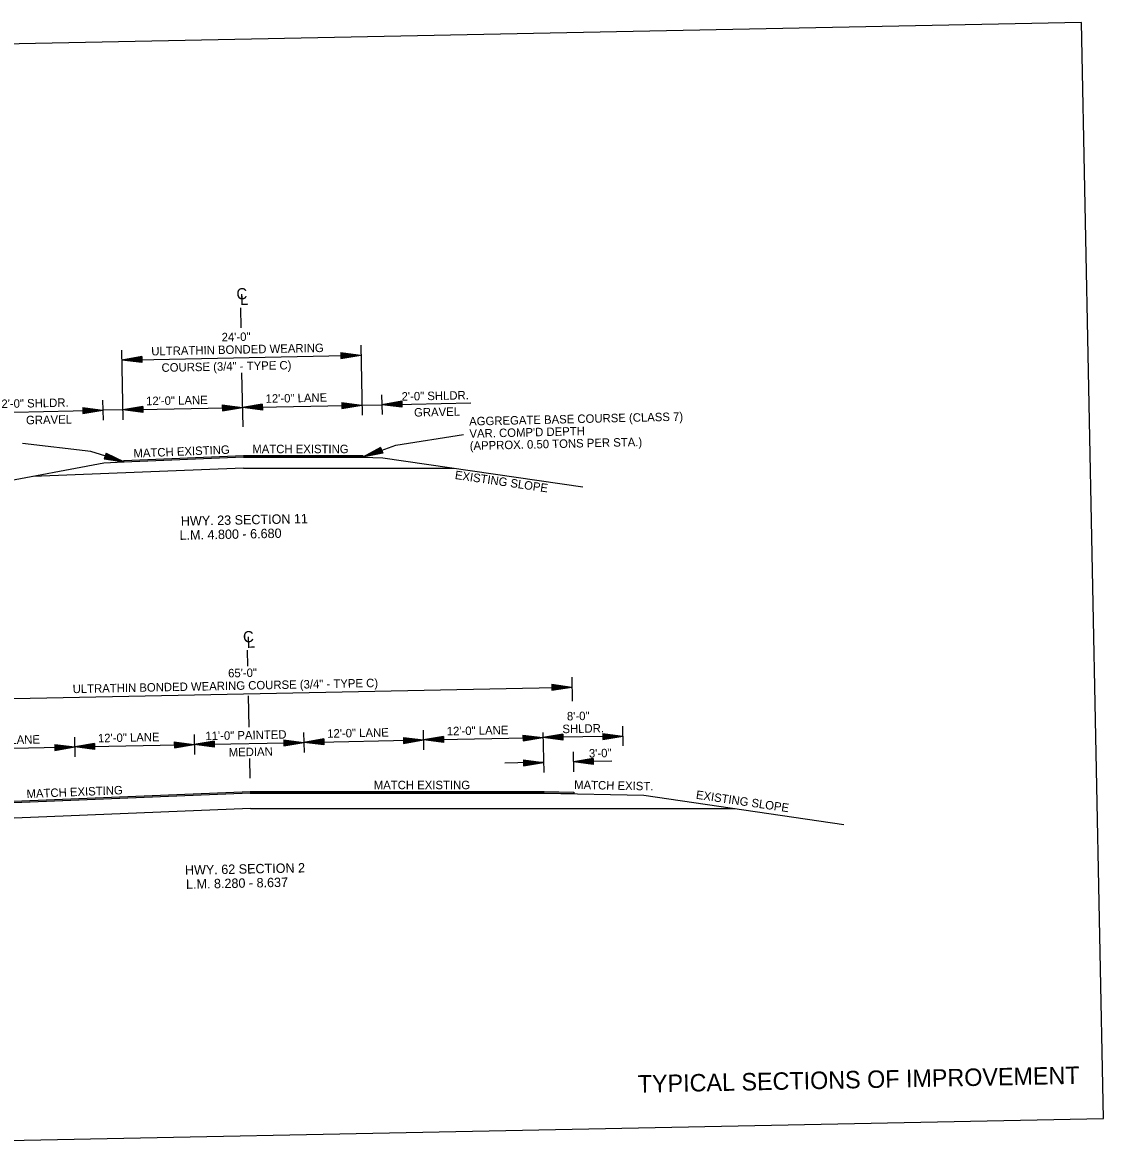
# Model space of a CAD drawing. Extents: x 174 to 869, y -36 to 177.
# Drawn here: x 760.3 to 868.8, y 64.1 to 177.4 of the extents above; entities that cross this region are included whole.
import ezdxf

# ---------------------------------------------------------------- set-up
doc = ezdxf.new("R2010")
doc.units = 0
for name, color, linetype in [('Default', 7, 'Continuous'), ('DSN_DRFT_Common-Annotations', 7, 'Continuous'), ('DSN_DRFT_Common-Line', 7, 'Continuous'), ('DSN_DRFT_Dimension', 7, 'Continuous'), ('SHET_Border-Text', 7, 'Continuous')]:
    doc.layers.add(name, color=color, linetype=linetype)

msp = doc.modelspace()

# ---------------------------------------------------------------- linework, layer by layer
at = {"layer": 'Default'}
for p, q in [((797.77, 135.02), (804.58, 136.09)), ((767.18, 134.4), (760.32, 135.21)), ((794.47, 133.82), (797.77, 135.02)), ((770.52, 133.35), (767.18, 134.4)), ((768.7, 134.24), (768.52, 133.66)), ((768.57, 133.81), (769.55, 133.65)), ((768.58, 133.86), (769.23, 133.75)), ((768.6, 133.9), (768.91, 133.85)), ((768.63, 133.99), (768.91, 133.85)), ((768.64, 134.04), (769.23, 133.75)), ((768.66, 134.09), (769.55, 133.65)), ((768.67, 134.14), (769.87, 133.55)), ((768.69, 134.19), (770.2, 133.45)), ((768.7, 134.24), (770.52, 133.35)), ((796.25, 134.79), (794.47, 133.82)), ((796.46, 134.22), (794.47, 133.82)), ((796.27, 134.74), (794.79, 133.94)), ((796.44, 134.27), (794.79, 133.94)), ((796.29, 134.69), (795.11, 134.05)), ((796.42, 134.32), (795.11, 134.05)), ((796.3, 134.64), (795.42, 134.17)), ((796.4, 134.36), (795.42, 134.17)), ((796.32, 134.6), (795.74, 134.28)), ((796.39, 134.41), (795.74, 134.28)), ((796.34, 134.55), (796.06, 134.4)), ((796.37, 134.46), (796.06, 134.4)), ((796.25, 134.79), (796.46, 134.22)), ((768.52, 133.66), (770.52, 133.35)), ((768.54, 133.71), (770.2, 133.45)), ((768.55, 133.76), (769.87, 133.55))]:
    msp.add_line(p, q, dxfattribs=at)
at = {"layer": 'DSN_DRFT_Common-Line'}
for p, q in [((782.17, 148.82), (782.21, 146.8)), ((770.25, 144.58), (770.39, 137.58)), ((794.25, 145.06), (794.39, 138.06)), ((782.3, 142.28), (782.41, 136.87)), ((768.35, 139.54), (768.39, 137.54)), ((796.35, 140.1), (796.39, 138.1)), ((782.47, 133.82), (770.48, 133.34)), ((782.47, 133.82), (794.47, 133.82)), ((794.47, 133.82), (796.47, 133.78)), ((768.48, 133.22), (748.55, 129.49)), ((782.49, 132.74), (761.39, 131.9)), ((770.48, 133.34), (768.48, 133.22)), ((782.49, 132.74), (803.61, 132.74)), ((796.47, 133.78), (816.54, 130.85)), ((782.86, 114.46), (782.89, 112.85)), ((815.42, 111.75), (815.47, 109.35)), ((782.95, 109.88), (783.01, 106.74)), ((820.52, 106.85), (820.56, 104.85)), ((765.53, 105.75), (765.57, 103.75)), ((777.53, 105.99), (777.57, 103.99)), ((788.52, 106.21), (788.56, 104.21)), ((800.52, 106.45), (800.56, 104.45)), ((812.53, 106.19), (812.61, 102.19)), ((783.08, 103.58), (783.11, 101.63)), ((815.57, 104.25), (815.61, 102.25)), ((783.14, 100.1), (753.66, 98.92)), ((783.14, 100.1), (812.65, 100.1)), ((812.65, 100.1), (822.66, 99.9)), ((822.66, 99.9), (842.72, 96.97)), ((783.18, 98.56), (734.56, 96.62)), ((783.18, 98.56), (831.83, 98.56))]:
    msp.add_line(p, q, dxfattribs=at)
for points in [[(696.61, 174.04), (698.81, 64.06), (868.78, 67.46), (866.58, 177.44)], [(794.47, 133.82), (782.47, 133.82), (770.48, 133.34), (770.47, 133.51), (782.47, 133.99), (794.47, 133.99)], [(812.65, 100.1), (783.14, 100.1), (753.66, 98.92), (750.67, 98.74), (750.66, 98.91), (753.66, 99.09), (783.14, 100.27), (812.65, 100.27), (815.65, 100.21), (815.65, 100.04)]]:
    msp.add_lwpolyline(points, close=True, dxfattribs=at)
at = {"layer": 'DSN_DRFT_Dimension'}
for p, q in [((770.27, 143.58), (794.27, 144.06)), ((792.26, 144.32), (794.27, 144.06)), ((792.26, 144.32), (792.27, 143.72)), ((792.26, 144.27), (793.93, 144.06)), ((792.26, 144.22), (793.59, 144.05)), ((792.27, 144.17), (793.26, 144.04)), ((792.27, 144.12), (792.92, 144.04)), ((792.27, 144.07), (792.58, 144.03)), ((792.27, 143.72), (794.27, 144.06)), ((792.27, 143.77), (793.93, 144.06)), ((792.27, 143.82), (793.59, 144.05)), ((792.27, 143.92), (792.92, 144.04)), ((792.27, 143.87), (793.26, 144.04)), ((792.27, 143.98), (792.58, 144.03)), ((772.27, 143.92), (770.27, 143.58)), ((772.28, 143.32), (770.27, 143.58)), ((772.27, 143.87), (770.61, 143.59)), ((772.28, 143.37), (770.61, 143.59)), ((772.27, 143.82), (770.95, 143.6)), ((772.28, 143.42), (770.95, 143.6)), ((772.27, 143.77), (771.28, 143.6)), ((772.28, 143.47), (771.28, 143.6)), ((772.27, 143.72), (771.62, 143.61)), ((772.27, 143.52), (771.62, 143.61)), ((772.27, 143.67), (771.96, 143.62)), ((772.27, 143.58), (771.96, 143.62)), ((772.27, 143.92), (772.28, 143.32)), ((759.44, 138.36), (768.37, 138.54)), ((766.37, 138.8), (768.37, 138.54)), ((766.37, 138.8), (766.38, 138.2)), ((766.37, 138.75), (768.04, 138.54)), ((766.37, 138.7), (767.7, 138.53)), ((766.37, 138.65), (767.36, 138.52)), ((766.37, 138.6), (767.02, 138.52)), ((766.37, 138.55), (766.69, 138.51)), ((766.37, 138.46), (766.69, 138.51)), ((766.38, 138.2), (768.37, 138.54)), ((766.38, 138.25), (768.04, 138.54)), ((766.38, 138.3), (767.7, 138.53)), ((766.38, 138.41), (767.02, 138.52)), ((766.38, 138.35), (767.36, 138.52)), ((770.37, 138.58), (768.37, 138.54)), ((772.37, 138.92), (770.37, 138.58)), ((770.37, 138.58), (782.37, 138.82)), ((772.38, 138.32), (770.37, 138.58)), ((772.37, 138.87), (770.71, 138.59)), ((772.38, 138.37), (770.71, 138.59)), ((772.37, 138.82), (771.05, 138.6)), ((772.38, 138.42), (771.05, 138.6)), ((772.37, 138.77), (771.38, 138.6)), ((772.38, 138.47), (771.38, 138.6)), ((772.37, 138.72), (771.72, 138.61)), ((772.37, 138.53), (771.72, 138.61)), ((772.37, 138.67), (772.06, 138.62)), ((772.37, 138.58), (772.06, 138.62)), ((772.37, 138.92), (772.38, 138.32)), ((780.36, 139.08), (782.37, 138.82)), ((780.36, 139.08), (780.38, 138.48)), ((780.37, 139.03), (782.04, 138.82)), ((780.37, 138.98), (781.69, 138.81)), ((780.37, 138.93), (781.36, 138.8)), ((780.37, 138.88), (781.02, 138.8)), ((780.37, 138.83), (780.69, 138.79)), ((780.37, 138.58), (781.69, 138.81)), ((780.37, 138.69), (781.02, 138.8)), ((780.37, 138.63), (781.36, 138.8)), ((780.37, 138.74), (780.69, 138.79)), ((780.38, 138.48), (782.37, 138.82)), ((780.38, 138.53), (782.04, 138.82)), ((784.36, 139.16), (782.37, 138.82)), ((782.37, 138.82), (794.37, 139.06)), ((784.38, 138.56), (782.37, 138.82)), ((784.37, 139.11), (782.7, 138.83)), ((784.38, 138.61), (782.7, 138.83)), ((784.37, 139.06), (783.05, 138.84)), ((784.37, 138.66), (783.05, 138.84)), ((784.37, 139.01), (783.38, 138.84)), ((784.37, 138.71), (783.38, 138.84)), ((784.37, 138.96), (783.72, 138.85)), ((784.37, 138.77), (783.72, 138.85)), ((784.37, 138.91), (784.05, 138.86)), ((784.37, 138.82), (784.05, 138.86)), ((784.36, 139.16), (784.38, 138.56)), ((792.36, 139.32), (794.37, 139.06)), ((792.36, 139.32), (792.37, 138.72)), ((792.36, 139.27), (794.03, 139.06)), ((792.36, 139.22), (793.69, 139.05)), ((792.37, 139.17), (793.36, 139.04)), ((792.37, 139.12), (793.02, 139.04)), ((792.37, 139.07), (792.68, 139.03)), ((792.37, 138.72), (794.37, 139.06)), ((792.37, 138.77), (794.03, 139.06)), ((792.37, 138.82), (793.69, 139.05)), ((792.37, 138.93), (793.02, 139.04)), ((792.37, 138.87), (793.36, 139.04)), ((792.37, 138.98), (792.68, 139.03)), ((794.37, 139.06), (796.37, 139.1)), ((798.36, 139.44), (796.37, 139.1)), ((796.37, 139.1), (805.31, 139.28)), ((798.37, 138.84), (796.37, 139.1)), ((798.36, 139.39), (796.7, 139.11)), ((798.37, 138.89), (796.7, 139.11)), ((798.36, 139.34), (797.05, 139.12)), ((798.37, 138.94), (797.05, 139.12)), ((798.36, 139.29), (797.38, 139.12)), ((798.37, 138.99), (797.38, 139.12)), ((798.37, 139.24), (797.72, 139.13)), ((798.37, 139.05), (797.72, 139.13)), ((798.37, 139.19), (798.05, 139.14)), ((798.37, 139.1), (798.05, 139.14)), ((798.36, 139.44), (798.37, 138.84)), ((750.45, 109.45), (815.44, 110.75)), ((813.44, 111.05), (815.44, 110.75)), ((813.44, 111.05), (813.44, 110.45)), ((813.44, 111), (815.1, 110.75)), ((813.44, 110.95), (814.76, 110.75)), ((813.44, 110.9), (814.43, 110.75)), ((813.44, 110.85), (814.09, 110.75)), ((813.44, 110.8), (813.75, 110.75)), ((813.44, 110.45), (815.44, 110.75)), ((813.44, 110.65), (814.09, 110.75)), ((813.44, 110.55), (814.76, 110.75)), ((813.44, 110.5), (815.1, 110.75)), ((813.44, 110.6), (814.43, 110.75)), ((813.44, 110.7), (813.75, 110.75)), ((786.54, 105.47), (788.54, 105.21)), ((786.54, 105.47), (786.55, 104.87)), ((790.54, 105.55), (788.54, 105.21)), ((788.54, 105.21), (800.54, 105.45)), ((790.54, 105.5), (788.88, 105.22)), ((790.54, 105.45), (789.22, 105.23)), ((790.54, 105.55), (790.55, 104.95)), ((798.54, 105.71), (800.54, 105.45)), ((798.54, 105.71), (798.55, 105.11)), ((798.54, 105.66), (800.21, 105.45)), ((798.54, 105.61), (799.86, 105.44)), ((798.54, 105.56), (799.53, 105.43)), ((798.54, 105.51), (799.19, 105.43)), ((798.54, 105.46), (798.86, 105.42)), ((798.55, 105.11), (800.54, 105.45)), ((798.55, 105.16), (800.21, 105.45)), ((802.54, 105.79), (800.54, 105.45)), ((800.54, 105.45), (812.54, 105.69)), ((802.55, 105.19), (800.54, 105.45)), ((802.54, 105.74), (800.88, 105.46)), ((802.55, 105.24), (800.88, 105.46)), ((802.54, 105.69), (801.22, 105.47)), ((802.55, 105.29), (801.22, 105.47)), ((802.54, 105.64), (801.55, 105.47)), ((802.54, 105.34), (801.55, 105.47)), ((802.54, 105.59), (801.89, 105.48)), ((802.54, 105.39), (801.89, 105.48)), ((802.54, 105.54), (802.23, 105.49)), ((802.54, 105.45), (802.23, 105.49)), ((802.54, 105.79), (802.55, 105.19)), ((810.53, 105.95), (812.54, 105.69)), ((810.53, 105.95), (810.55, 105.35)), ((810.53, 105.9), (812.21, 105.69)), ((810.54, 105.85), (811.86, 105.68)), ((810.54, 105.8), (811.53, 105.67)), ((810.54, 105.75), (811.19, 105.67)), ((810.54, 105.7), (810.86, 105.66)), ((810.54, 105.4), (812.21, 105.69)), ((810.54, 105.45), (811.86, 105.68)), ((810.54, 105.55), (811.19, 105.67)), ((810.54, 105.5), (811.53, 105.67)), ((810.54, 105.61), (810.86, 105.66)), ((810.55, 105.35), (812.54, 105.69)), ((814.53, 106.03), (812.54, 105.69)), ((820.54, 105.85), (812.54, 105.69)), ((814.54, 105.43), (812.54, 105.69)), ((814.53, 105.98), (812.87, 105.7)), ((814.54, 105.48), (812.87, 105.7)), ((814.53, 105.93), (813.22, 105.71)), ((814.54, 105.53), (813.22, 105.71)), ((814.54, 105.88), (813.55, 105.71)), ((814.54, 105.58), (813.55, 105.71)), ((814.54, 105.83), (813.89, 105.72)), ((814.54, 105.63), (813.89, 105.72)), ((814.54, 105.78), (814.22, 105.73)), ((814.54, 105.69), (814.22, 105.73)), ((814.53, 106.03), (814.54, 105.43)), ((818.53, 106.11), (820.54, 105.85)), ((818.53, 106.11), (818.54, 105.51)), ((818.53, 106.06), (820.2, 105.85)), ((818.53, 106.01), (819.86, 105.84)), ((818.53, 105.96), (819.53, 105.83)), ((818.54, 105.91), (819.19, 105.83)), ((818.54, 105.86), (818.85, 105.82)), ((818.54, 105.51), (820.54, 105.85)), ((818.54, 105.56), (820.2, 105.85)), ((818.54, 105.61), (819.86, 105.84)), ((818.54, 105.71), (819.19, 105.83)), ((818.54, 105.66), (819.53, 105.83)), ((818.54, 105.77), (818.85, 105.82)), ((753.55, 104.51), (765.55, 104.75)), ((763.54, 105.01), (765.55, 104.75)), ((763.54, 105.01), (763.55, 104.41)), ((763.54, 104.96), (765.21, 104.75)), ((763.54, 104.91), (764.87, 104.74)), ((763.55, 104.86), (764.54, 104.73)), ((763.55, 104.81), (764.2, 104.73)), ((763.55, 104.76), (763.86, 104.72)), ((763.55, 104.41), (765.55, 104.75)), ((763.55, 104.46), (765.21, 104.75)), ((763.55, 104.51), (764.87, 104.74)), ((763.55, 104.61), (764.2, 104.73)), ((763.55, 104.56), (764.54, 104.73)), ((763.55, 104.67), (763.86, 104.72)), ((767.54, 105.09), (765.55, 104.75)), ((765.55, 104.75), (777.55, 104.99)), ((767.55, 104.49), (765.55, 104.75)), ((767.54, 105.04), (765.88, 104.76)), ((767.55, 104.54), (765.88, 104.76)), ((767.54, 104.99), (766.23, 104.77)), ((767.55, 104.59), (766.23, 104.77)), ((767.55, 104.94), (766.56, 104.77)), ((767.55, 104.64), (766.56, 104.77)), ((767.55, 104.89), (766.9, 104.78)), ((767.55, 104.69), (766.9, 104.78)), ((767.55, 104.84), (767.23, 104.79)), ((767.55, 104.75), (767.23, 104.79)), ((767.54, 105.09), (767.55, 104.49)), ((775.54, 105.25), (777.55, 104.99)), ((775.54, 105.25), (775.55, 104.65)), ((775.54, 105.2), (777.21, 104.99)), ((775.54, 105.15), (776.87, 104.98)), ((775.54, 105.1), (776.54, 104.97)), ((775.54, 105.05), (776.2, 104.97)), ((775.55, 105), (775.86, 104.96)), ((775.55, 104.65), (777.55, 104.99)), ((775.55, 104.7), (777.21, 104.99)), ((775.55, 104.75), (776.87, 104.98)), ((775.55, 104.85), (776.2, 104.97)), ((775.55, 104.8), (776.54, 104.97)), ((775.55, 104.91), (775.86, 104.96)), ((779.54, 105.33), (777.55, 104.99)), ((777.55, 104.99), (788.54, 105.21)), ((779.55, 104.73), (777.55, 104.99)), ((779.54, 105.28), (777.88, 105)), ((779.55, 104.78), (777.88, 105)), ((779.54, 105.23), (778.22, 105.01)), ((779.55, 104.83), (778.22, 105.01)), ((779.54, 105.18), (778.56, 105.01)), ((779.55, 104.88), (778.56, 105.01)), ((779.54, 105.13), (778.9, 105.02)), ((779.55, 104.93), (778.9, 105.02)), ((779.54, 105.08), (779.23, 105.03)), ((779.55, 104.99), (779.23, 105.03)), ((779.54, 105.33), (779.55, 104.73)), ((786.54, 105.42), (788.21, 105.21)), ((786.54, 105.37), (787.87, 105.2)), ((786.54, 105.32), (787.53, 105.19)), ((786.54, 105.27), (787.19, 105.19)), ((786.54, 105.22), (786.86, 105.18)), ((786.55, 104.87), (788.54, 105.21)), ((786.55, 104.92), (788.21, 105.21)), ((786.55, 104.97), (787.87, 105.2)), ((786.55, 105.07), (787.19, 105.19)), ((786.55, 105.02), (787.53, 105.19)), ((786.55, 105.13), (786.86, 105.18)), ((790.55, 104.95), (788.54, 105.21)), ((790.55, 105), (788.88, 105.22)), ((790.55, 105.05), (789.22, 105.23)), ((790.54, 105.4), (789.55, 105.23)), ((790.55, 105.1), (789.55, 105.23)), ((790.54, 105.35), (789.89, 105.24)), ((790.55, 105.15), (789.89, 105.24)), ((790.54, 105.3), (790.23, 105.25)), ((790.54, 105.21), (790.23, 105.25)), ((798.54, 105.31), (799.19, 105.43)), ((798.54, 105.26), (799.53, 105.43)), ((798.54, 105.37), (798.86, 105.42)), ((798.55, 105.21), (799.86, 105.44)), ((812.59, 103.21), (808.72, 103.14)), ((810.58, 103.45), (812.59, 103.19)), ((810.58, 103.45), (810.6, 102.85)), ((810.58, 103.4), (812.26, 103.19)), ((810.59, 103.35), (811.91, 103.18)), ((810.59, 103.3), (811.58, 103.17)), ((810.59, 103.25), (811.24, 103.17)), ((810.59, 103.2), (810.91, 103.16)), ((810.59, 102.9), (812.26, 103.19)), ((810.59, 102.95), (811.91, 103.18)), ((810.6, 102.85), (812.59, 103.19)), ((817.58, 103.59), (815.59, 103.25)), ((819.45, 103.33), (815.59, 103.25)), ((817.59, 102.99), (815.59, 103.25)), ((817.58, 103.54), (815.92, 103.26)), ((817.59, 103.04), (815.92, 103.26)), ((817.58, 103.49), (816.27, 103.27)), ((817.59, 103.09), (816.27, 103.27)), ((817.59, 103.44), (816.6, 103.27)), ((817.59, 103.14), (816.6, 103.27)), ((817.59, 103.39), (816.94, 103.28)), ((817.59, 103.2), (816.94, 103.28)), ((817.59, 103.34), (817.27, 103.29)), ((817.59, 103.25), (817.27, 103.29)), ((817.58, 103.59), (817.59, 102.99)), ((810.59, 103.06), (811.24, 103.17)), ((810.59, 103), (811.58, 103.17)), ((810.59, 103.11), (810.91, 103.16))]:
    msp.add_line(p, q, dxfattribs=at)

# ---------------------------------------------------------------- texts
at = {"layer": 'Default'}
for s, height, rotation, p in [('AGGREGATE BASE COURSE (CLASS 7)', 0.85, 1.3198, (805.14, 137)), ("VAR. COMP'D DEPTH", 0.85, 1.3198, (805.17, 135.77)), ('(APPROX. 0.50 TONS PER STA.)', 0.85, 1.3198, (805.2, 134.55)), ('C', 1.12, 2.2915, (782.46, 115.24)), ('L', 1.12, 2.2915, (782.82, 114.69))]:
    msp.add_text(s, height=height, rotation=rotation, dxfattribs=at).set_placement(p)
at = {"layer": 'DSN_DRFT_Common-Annotations'}
for s, height, rotation, p in [('C', 1.12, 2.2915, (781.8, 149.65)), ('L', 1.12, 2.2915, (782.16, 149.09)), ('24\'-0"', 0.85, 1.1458, (780.3, 145.45)), ('ULTRATHIN BONDED WEARING', 0.85, 1.1458, (773.24, 144.04)), ('COURSE (3/4" - TYPE C)', 0.85, 1.1458, (774.27, 142.39)), ('2\'-0" SHLDR.', 0.85, 1.1458, (758.2, 138.76)), ('12\'-0" LANE', 0.85, 1.1458, (772.72, 139.04)), ('12\'-0" LANE', 0.85, 1.1458, (784.71, 139.28)), ('2\'-0" SHLDR.', 0.85, 1.1458, (798.36, 139.5)), ('GRAVEL', 0.85, 1.1458, (799.61, 137.9)), ('GRAVEL', 0.85, 1.1458, (760.67, 137.12)), ('MATCH EXISTING', 0.85, 2.2915, (771.46, 133.79)), ('EXISTING SLOPE', 0.85, 351.6838, (803.66, 131.65)), ('HWY. 23 SECTION 11', 0.943, 1.1458, (776.21, 126.95)), ('L.M. 4.800 - 6.680', 0.943, 1.1458, (776.08, 125.53)), ('65\'-0"', 0.85, 1.1458, (780.95, 111.73)), ('ULTRATHIN BONDED WEARING COURSE (3/4" - TYPE C)', 0.85, 1.1458, (765.35, 110.15)), ('8\'-0"', 0.85, 1.1458, (814.95, 107.41)), ('12\'-0" LANE', 0.85, 1.1458, (790.89, 105.67)), ('12\'-0" LANE', 0.85, 1.1458, (802.89, 105.91)), ('SHLDR.', 0.85, 1.1458, (814.5, 106.13)), ('12\'-0" LANE', 0.85, 1.1458, (755.89, 104.97)), ('12\'-0" LANE', 0.85, 1.1458, (767.89, 105.21)), ('11\'-0" PAINTED', 0.85, 1.1458, (778.67, 105.43)), ('MEDIAN', 0.85, 1.1458, (781.01, 103.79)), (' 3\'-0"', 0.85, 1.1458, (816.84, 103.68)), ('MATCH EXIST.', 0.85, 358.8552, (815.66, 100.54)), ('MATCH EXISTING', 0.85, 2.2915, (760.73, 99.62)), ('EXISTING SLOPE', 0.85, 351.6838, (827.85, 99.56)), ('HWY. 62 SECTION 2', 0.943, 1.1458, (776.62, 91.92)), ('L.M. 8.280 - 8.637', 0.943, 1.1458, (776.73, 90.51))]:
    msp.add_text(s, height=height, rotation=rotation, dxfattribs=at).set_placement(p)
for p in [(783.37, 134.23), (795.56, 100.51)]:
    msp.add_text('MATCH EXISTING', height=0.85, dxfattribs=at).set_placement(p)
at = {"layer": 'SHET_Border-Text'}
msp.add_text('TYPICAL SECTIONS OF IMPROVEMENT', height=1.75, rotation=1.1458, dxfattribs=at).set_placement((822.07, 70.06))

doc.saveas('drawing.dxf')
